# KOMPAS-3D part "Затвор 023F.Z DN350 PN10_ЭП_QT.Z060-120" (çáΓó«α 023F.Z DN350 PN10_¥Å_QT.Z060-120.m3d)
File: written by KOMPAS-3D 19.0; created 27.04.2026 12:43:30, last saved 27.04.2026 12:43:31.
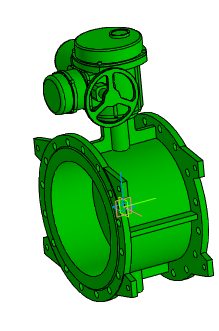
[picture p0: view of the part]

Document properties: Полное имя файла: Затвор 023F.Z DN350 PN10 + электропривод QT.Z060-120.a3d

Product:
- Part/product: Затвор 023F.Z DN350 PN10_ЭП_QT.Z060-120
    Масса: 183.053
  - Body: Тело 1
      Масса: 183.352

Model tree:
1. Операция без истории:1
